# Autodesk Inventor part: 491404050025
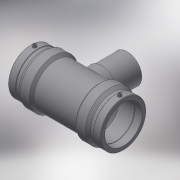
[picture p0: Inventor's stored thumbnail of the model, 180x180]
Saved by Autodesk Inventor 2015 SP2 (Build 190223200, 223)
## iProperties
Created: 2017-06
Part Number: 491404050025
Material: Generic
Description: PLASSON REDUCING TEE 50x25x50
Document SubType Name: Modeling
Designer: KIM
Mass: 230.814 g
Surface Area: 630.555 cm^2
Volume: 230.814 cm^3
Density: 1 g/cm^3
Appearance: Default
Author: KIM
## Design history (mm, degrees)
derived "491404.ipt"
feature "Solid1::491404.ipt"
tag "TaggingFeature1"
body "Solid1"
other parameters: "d0" = 139, "d2" = 68, "d3" = 48, "d4" = 27.8, "d5" = 61.2, "d6" = 47.5, "d8" = 168 deg, "d10" = 19.2, "d11" = 6.4, "d13" = 139, "d14" = 17.6296, "d17" = 45, "d19" = 3.52592, "d20" = 168 deg, "d22" = 63.24, "d23" = 68, "d25" = 135 deg, "d26" = 97.3, "d29" = 52, "d30" = 15, "d31" = 55.6, "d34" = 5 deg, "d35" = 15, "d39" = 5 deg, "d41" = 4, "d42" = 14, "d43" = 0, "d45" = 4, "d46" = 6, "d47" = 0, "d48" = -78, "d49" = 25, "d51" = 0, "d54" = 0, "d55" = 61.2, "d56" = 68, "d57" = 48.65, "d58" = 135 deg, "d59" = 48, "d60" = 48, "d61" = 135 deg, "d62" = 78, "d72" = 63.245, "d73" = 31.6225, "d74" = -78, "d75" = 26.25, "d77" = 0, "d80" = 0, "d81" = 25, "d82" = 44, "d83" = 0, "d84" = 3, "d85" = 0, "d86" = 16, "d87" = 61.9752, "d88" = 6.4, "d89" = 3, "d90" = 0, "L_" = 139, "L_1" = 48, "D_" = 68, "A_" = 52, "d_2" = 12, "H_" = 78, "d_1" = 25
